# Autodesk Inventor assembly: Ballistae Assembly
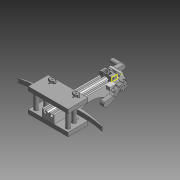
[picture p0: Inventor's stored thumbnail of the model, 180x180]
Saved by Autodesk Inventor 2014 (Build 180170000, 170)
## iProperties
Created: 2013-11
Part Number: Ballistae Assembly
Document SubType Name: Assembly
Designer: 603839
Author: 603839
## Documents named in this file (12)
- U:\Dominic Cupo Design Studio\Tabletop Ballistae\Ballistae Assembly.iam
- U:\Dominic Cupo Design Studio\Tabletop Ballistae\Main Body.ipt
- U:\Dominic Cupo Design Studio\Tabletop Ballistae\Gusset Plates.ipt
- U:\Dominic Cupo Design Studio\Tabletop Ballistae\Support Rods.ipt
- U:\Dominic Cupo Design Studio\Tabletop Ballistae\Crank.ipt
- U:\Dominic Cupo Design Studio\Tabletop Ballistae\Ratchet.ipt
- U:\Dominic Cupo Design Studio\Tabletop Ballistae\String Pulley.ipt
- U:\Dominic Cupo Design Studio\Tabletop Ballistae\Pull Shoe.ipt
- U:\Dominic Cupo Design Studio\Tabletop Ballistae\String holder.ipt
- U:\Dominic Cupo Design Studio\Tabletop Ballistae\Retaining Nuts.ipt
- U:\Dominic Cupo Design Studio\Tabletop Ballistae\Rachet Prawl.ipt
- U:\Dominic Cupo Design Studio\Tabletop Ballistae\Bow Arms.ipt
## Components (19 placed, 11 different names)
1. Gusset Plates:1 — Mate:2, Mate:3, Mate:4, Mate:5, Insert:7, Insert:8, Mate:7, Flush:1, Flush:2
2. Gusset Plates:2 — Mate:6, Insert:9, Insert:10
3. Support Rods:1 — Mate:2
4. Support Rods:2 — Mate:3
5. Support Rods:3 — Mate:4
6. Support Rods:4 — Mate:5, Mate:6
7. Crank:1 — Insert:22
8. Ratchet:2 — Insert:18
9. String Pulley:1
10. Pull Shoe:1 — Mate:8, Flush:3, Insert:21
11. String holder:1 — Insert:21
12. Retaining Nuts:1 — Insert:9, Insert:17
13. Retaining Nuts:2 — Insert:10, Insert:16
14. Retaining Nuts:3 — Insert:7
15. Retaining Nuts:4 — Insert:8
16. Main Body:1 — Mate:7, Flush:1, Flush:2, Mate:8, Flush:3, Insert:18, Insert:20, Insert:22
17. Bow Arms:1 — Insert:16
18. Bow Arms:2 — Insert:17
19. Rachet Prawl:2 — Insert:20
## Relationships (20: Insert 10, Mate 7, Flush 3)
- Mate:2: Gusset Plates:1 ↔ Support Rods:1
- Mate:3: Gusset Plates:1 ↔ Support Rods:2
- Mate:4: Gusset Plates:1 ↔ Support Rods:3
- Mate:5: Gusset Plates:1 ↔ Support Rods:4
- Mate:6: Gusset Plates:2 ↔ Support Rods:4
- Insert:7: Gusset Plates:1 ↔ Retaining Nuts:3
- Insert:8: Gusset Plates:1 ↔ Retaining Nuts:4
- Insert:9: Gusset Plates:2 ↔ Retaining Nuts:1
- Insert:10: Gusset Plates:2 ↔ Retaining Nuts:2
- Mate:7: Gusset Plates:1 ↔ Main Body:1
- Flush:1: Gusset Plates:1 ↔ Main Body:1
- Flush:2: Gusset Plates:1 ↔ Main Body:1
- Mate:8: Pull Shoe:1 ↔ Main Body:1
- Flush:3: Pull Shoe:1 ↔ Main Body:1
- Insert:16: Retaining Nuts:2 ↔ Bow Arms:1
- Insert:17: Retaining Nuts:1 ↔ Bow Arms:2
- Insert:18: Ratchet:2 ↔ Main Body:1
- Insert:20: Main Body:1 ↔ Rachet Prawl:2
- Insert:21: Pull Shoe:1 ↔ String holder:1
- Insert:22: Crank:1 ↔ Main Body:1
